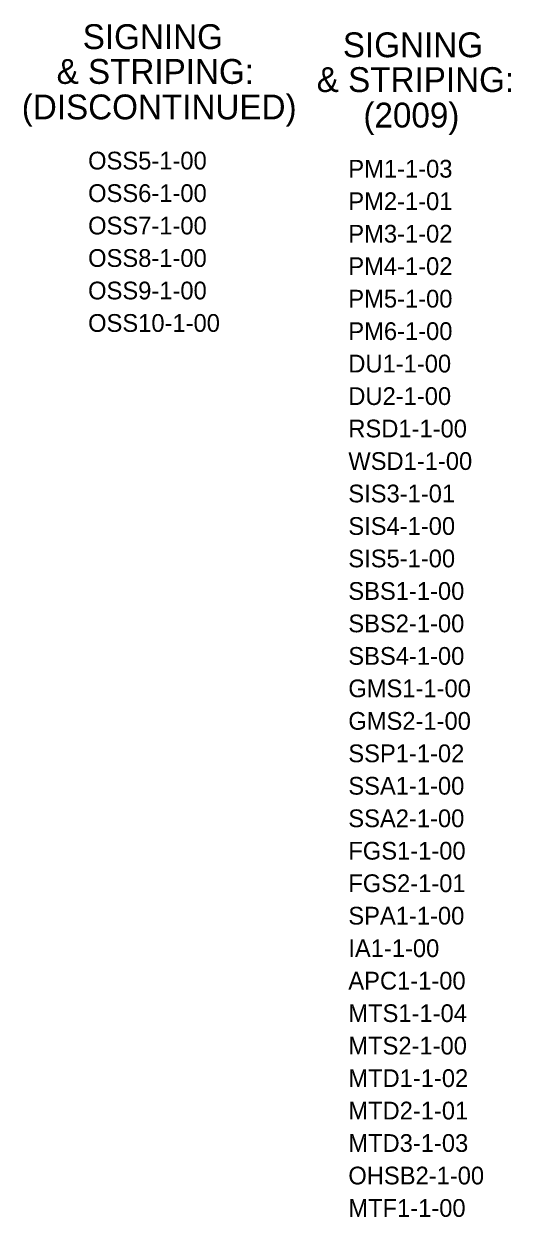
# Model space of a CAD drawing. Extents: x 11.3 to 109.4, y -18.4 to 58.
# Drawn here: x 73.82 to 80.69, y -18.43 to -1.62 of the extents above; entities that cross this region are included whole.
import ezdxf

# ---------------------------------------------------------------- set-up
doc = ezdxf.new("R2010")
doc.units = 0
doc.layers.add('PR_Improvements_Txt', color=7, linetype='Continuous')

msp = doc.modelspace()

# ---------------------------------------------------------------- texts
at = {"layer": 'PR_Improvements_Txt'}
for s, height, p in [('SIGNING', 0.35, (74.646, -1.976)), ('SIGNING', 0.35, (78.313, -2.091)), ('& STRIPING:', 0.35, (74.278, -2.466)), ('& STRIPING:', 0.35, (77.945, -2.581)), ('(DISCONTINUED)', 0.35, (73.787, -2.966)), ('(2009)', 0.35, (78.603, -3.081)), ('OSS5-1-00', 0.25, (74.722, -3.672)), ('PM1-1-03', 0.25, (78.39, -3.787)), ('OSS6-1-00', 0.25, (74.722, -4.13)), ('PM2-1-01', 0.25, (78.39, -4.244)), ('OSS7-1-00', 0.25, (74.722, -4.587)), ('PM3-1-02', 0.25, (78.39, -4.702)), ('OSS8-1-00', 0.25, (74.722, -5.044)), ('PM4-1-02', 0.25, (78.39, -5.159)), ('OSS9-1-00', 0.25, (74.722, -5.502)), ('PM5-1-00', 0.25, (78.39, -5.617)), ('OSS10-1-00', 0.25, (74.722, -5.959)), ('PM6-1-00', 0.25, (78.39, -6.074)), ('DU1-1-00', 0.25, (78.39, -6.531)), ('DU2-1-00', 0.25, (78.39, -6.989)), ('RSD1-1-00', 0.25, (78.39, -7.446)), ('WSD1-1-00', 0.25, (78.39, -7.904)), ('SIS3-1-01', 0.25, (78.39, -8.361)), ('SIS4-1-00', 0.25, (78.39, -8.819)), ('SIS5-1-00', 0.25, (78.39, -9.276)), ('SBS1-1-00', 0.25, (78.39, -9.734)), ('SBS2-1-00', 0.25, (78.39, -10.191)), ('SBS4-1-00', 0.25, (78.39, -10.649)), ('GMS1-1-00', 0.25, (78.39, -11.106)), ('GMS2-1-00', 0.25, (78.39, -11.564)), ('SSP1-1-02', 0.25, (78.39, -12.021)), ('SSA1-1-00', 0.25, (78.39, -12.478)), ('SSA2-1-00', 0.25, (78.39, -12.936)), ('FGS1-1-00', 0.25, (78.39, -13.393)), ('FGS2-1-01', 0.25, (78.39, -13.851)), ('SPA1-1-00', 0.25, (78.39, -14.308)), ('IA1-1-00', 0.25, (78.39, -14.766)), ('APC1-1-00', 0.25, (78.39, -15.223)), ('MTS1-1-04', 0.25, (78.39, -15.681)), ('MTS2-1-00', 0.25, (78.39, -16.138)), ('MTD1-1-02', 0.25, (78.39, -16.596)), ('MTD2-1-01', 0.25, (78.39, -17.053)), ('MTD3-1-03', 0.25, (78.39, -17.51)), ('OHSB2-1-00', 0.25, (78.39, -17.968)), ('MTF1-1-00', 0.25, (78.39, -18.425))]:
    msp.add_text(s, height=height, dxfattribs=at).set_placement(p)

doc.saveas('drawing.dxf')
